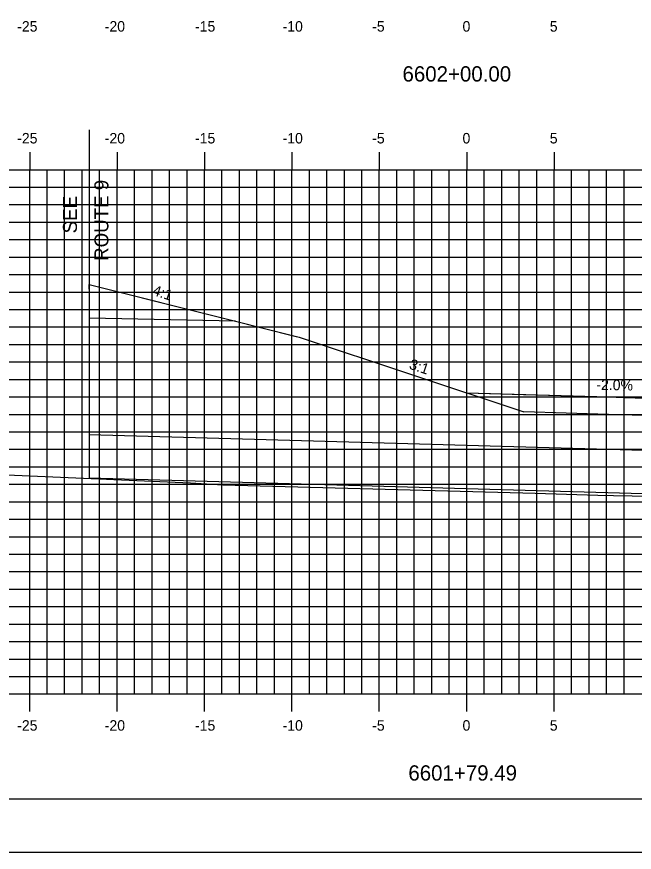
# Model space of a CAD drawing. Extents: x 1723961 to 1724133, y 459560 to 459670.
# Drawn here: x 1724018.73 to 1724054.06, y 459559.55 to 459607.37 of the extents above; entities that cross this region are included whole.
import ezdxf

# ---------------------------------------------------------------- set-up
doc = ezdxf.new("R2010")
doc.units = 0
for name, color, linetype in [('ANNOTATION', 7, 'Continuous'), ('BORDER', 7, 'Continuous'), ('D_Drainage_Culvert', 7, 'Continuous'), ('D_Roadway_Centerline', 7, 'Continuous'), ('D_Roadway_Drive_Gravel', 7, 'Continuous'), ('D_Roadway_Edge_Shoulder', 7, 'Continuous'), ('D_Roadway_SlopeLines', 7, 'Continuous'), ('D_Roadway_SubGrade', 7, 'Continuous'), ('H_V ANNOTATION', 7, 'Continuous'), ('MAJOR', 7, 'Continuous'), ('MINOR', 7, 'Continuous'), ('PLOT BOUNDARY', 7, 'Continuous'), ('S_Roadway_Centerline', 7, 'Continuous')]:
    doc.layers.add(name, color=color, linetype=linetype)

msp = doc.modelspace()

# ---------------------------------------------------------------- linework, layer by layer
msp.add_lwpolyline([(1724044.473, 459585.843), (1724047.721, 459585.749), (1724049.861, 459585.686), (1724052.573, 459585.607), (1724053.432, 459585.582), (1724054.109, 459585.562), (1724059.84, 459585.395), (1724060.497, 459585.376), (1724060.574, 459585.374), (1724060.673, 459585.371), (1724062.76, 459584.665), (1724063.904, 459584.277), (1724067.586, 459583.03)])
at = {"layer": 'BORDER'}
msp.add_lwpolyline([(1723969.473, 459562.613), (1724129.473, 459562.613), (1724129.473, 459667.613), (1723969.473, 459667.613)], close=True, dxfattribs=at)
at = {"layer": 'D_Drainage_Culvert'}
msp.add_lwpolyline([(1724022.879, 459583.464), (1724077.547, 459581.919), (1724077.48, 459579.42), (1724022.879, 459580.963)], dxfattribs=at)
at = {"layer": 'D_Roadway_Centerline'}
msp.add_lwpolyline([(1724022.879, 459592.034), (1724030.709, 459590.077), (1724031.241, 459589.944), (1724034.647, 459589.092), (1724034.879, 459589.034), (1724047.738, 459584.748)], dxfattribs=at)
at = {"layer": 'D_Roadway_Drive_Gravel'}
msp.add_lwpolyline([(1724044.473, 459585.836), (1724044.473, 459585.843), (1724052.573, 459585.607), (1724060.673, 459585.371), (1724063.904, 459584.277), (1724060.673, 459584.371), (1724052.573, 459584.607), (1724047.738, 459584.748)], dxfattribs=at)
at = {"layer": 'D_Roadway_Edge_Shoulder'}
msp.add_line((1724022.879, 459592.034), (1724022.879, 459591.784), dxfattribs=at)
msp.add_line((1724022.879, 459592.034), (1724022.879, 459591.784), dxfattribs=at)
at = {"layer": 'D_Roadway_SlopeLines'}
msp.add_lwpolyline([(1724022.879, 459592.034), (1724034.879, 459589.034), (1724047.738, 459584.748)], dxfattribs=at)
msp.add_lwpolyline([(1724022.879, 459592.034), (1724034.879, 459589.034), (1724047.738, 459584.748)], dxfattribs=at)
msp.add_lwpolyline([(1724022.879, 459592.034), (1724034.879, 459589.034), (1724047.738, 459584.748)], dxfattribs=at)
msp.add_lwpolyline([(1724022.879, 459592.034), (1724034.879, 459589.034), (1724047.738, 459584.748)], dxfattribs=at)
msp.add_lwpolyline([(1724022.879, 459592.034), (1724034.879, 459589.034), (1724047.738, 459584.748)], dxfattribs=at)
msp.add_lwpolyline([(1724022.879, 459592.034), (1724034.879, 459589.034), (1724047.738, 459584.748)], dxfattribs=at)
msp.add_lwpolyline([(1724022.879, 459592.034), (1724034.879, 459589.034), (1724047.738, 459584.748)], dxfattribs=at)
at = {"layer": 'D_Roadway_SubGrade'}
for p, q in [((1724022.879, 459600.893), (1724022.879, 459590.111)), ((1724022.879, 459590.111), (1724022.879, 459580.941))]:
    msp.add_line(p, q, dxfattribs=at)
msp.add_lwpolyline([(1724022.879, 459591.784), (1724022.879, 459592.034), (1724031.241, 459589.944), (1724022.879, 459590.111)], dxfattribs=at)
msp.add_lwpolyline([(1724022.879, 459591.784), (1724022.879, 459592.034), (1724031.241, 459589.944), (1724022.879, 459590.111)], dxfattribs=at)
msp.add_lwpolyline([(1724022.879, 459591.784), (1724022.879, 459592.034), (1724031.241, 459589.944), (1724022.879, 459590.111)], dxfattribs=at)
msp.add_lwpolyline([(1724022.879, 459591.784), (1724022.879, 459592.034), (1724031.241, 459589.944), (1724022.879, 459590.111)], dxfattribs=at)
at = {"layer": 'MAJOR'}
for p, q in [((1724019.473, 459599.615), (1724019.473, 459598.613)), ((1724024.473, 459599.615), (1724024.473, 459598.613)), ((1724029.473, 459599.615), (1724029.473, 459598.613)), ((1724034.473, 459599.615), (1724034.473, 459598.613)), ((1724039.473, 459599.615), (1724039.473, 459598.613)), ((1724044.473, 459599.615), (1724044.473, 459598.613)), ((1724049.473, 459599.615), (1724049.473, 459598.613)), ((1723974.473, 459598.613), (1724114.473, 459598.613)), ((1723974.473, 459598.613), (1724114.473, 459598.613)), ((1724019.473, 459568.613), (1724019.473, 459598.613)), ((1724024.473, 459568.613), (1724024.473, 459598.613)), ((1724029.473, 459568.613), (1724029.473, 459598.613)), ((1724034.473, 459568.613), (1724034.473, 459598.613)), ((1724039.473, 459568.613), (1724039.473, 459598.613)), ((1724044.473, 459568.613), (1724044.473, 459598.613)), ((1724049.473, 459568.613), (1724049.473, 459598.613)), ((1723974.473, 459593.613), (1724114.473, 459593.613)), ((1723974.473, 459588.613), (1724114.473, 459588.613)), ((1723974.473, 459583.613), (1724114.473, 459583.613)), ((1723974.473, 459578.613), (1724114.473, 459578.613)), ((1723974.473, 459573.613), (1724114.473, 459573.613)), ((1723974.473, 459568.613), (1724114.473, 459568.613)), ((1723974.473, 459568.613), (1724114.473, 459568.613)), ((1724019.473, 459567.611), (1724019.473, 459568.613)), ((1724024.473, 459567.611), (1724024.473, 459568.613)), ((1724029.473, 459567.611), (1724029.473, 459568.613)), ((1724034.473, 459567.611), (1724034.473, 459568.613)), ((1724039.473, 459567.611), (1724039.473, 459568.613)), ((1724044.473, 459567.611), (1724044.473, 459568.613)), ((1724049.473, 459567.611), (1724049.473, 459568.613))]:
    msp.add_line(p, q, dxfattribs=at)
at = {"layer": 'MINOR'}
for p, q in [((1724020.473, 459568.613), (1724020.473, 459598.613)), ((1724021.473, 459568.613), (1724021.473, 459598.613)), ((1724022.473, 459568.613), (1724022.473, 459598.613)), ((1724023.473, 459568.613), (1724023.473, 459598.613)), ((1724025.473, 459568.613), (1724025.473, 459598.613)), ((1724026.473, 459568.613), (1724026.473, 459598.613)), ((1724027.473, 459568.613), (1724027.473, 459598.613)), ((1724028.473, 459568.613), (1724028.473, 459598.613)), ((1724030.473, 459568.613), (1724030.473, 459598.613)), ((1724031.473, 459568.613), (1724031.473, 459598.613)), ((1724032.473, 459568.613), (1724032.473, 459598.613)), ((1724033.473, 459568.613), (1724033.473, 459598.613)), ((1724035.473, 459568.613), (1724035.473, 459598.613)), ((1724036.473, 459568.613), (1724036.473, 459598.613)), ((1724037.473, 459568.613), (1724037.473, 459598.613)), ((1724038.473, 459568.613), (1724038.473, 459598.613)), ((1724040.473, 459568.613), (1724040.473, 459598.613)), ((1724041.473, 459568.613), (1724041.473, 459598.613)), ((1724042.473, 459568.613), (1724042.473, 459598.613)), ((1724043.473, 459568.613), (1724043.473, 459598.613)), ((1724045.473, 459568.613), (1724045.473, 459598.613)), ((1724046.473, 459568.613), (1724046.473, 459598.613)), ((1724047.473, 459568.613), (1724047.473, 459598.613)), ((1724048.473, 459568.613), (1724048.473, 459598.613)), ((1724050.473, 459568.613), (1724050.473, 459598.613)), ((1724051.473, 459568.613), (1724051.473, 459598.613)), ((1724052.473, 459568.613), (1724052.473, 459598.613)), ((1724053.473, 459568.613), (1724053.473, 459598.613)), ((1723974.473, 459597.613), (1724114.473, 459597.613)), ((1723974.473, 459596.613), (1724114.473, 459596.613)), ((1723974.473, 459595.613), (1724114.473, 459595.613)), ((1723974.473, 459594.613), (1724114.473, 459594.613)), ((1723974.473, 459592.613), (1724114.473, 459592.613)), ((1723974.473, 459591.613), (1724114.473, 459591.613)), ((1723974.473, 459590.613), (1724114.473, 459590.613)), ((1723974.473, 459589.613), (1724114.473, 459589.613)), ((1723974.473, 459587.613), (1724114.473, 459587.613)), ((1723974.473, 459586.613), (1724114.473, 459586.613)), ((1723974.473, 459585.613), (1724114.473, 459585.613)), ((1723974.473, 459584.613), (1724114.473, 459584.613)), ((1723974.473, 459582.613), (1724114.473, 459582.613)), ((1723974.473, 459581.613), (1724114.473, 459581.613)), ((1723974.473, 459580.613), (1724114.473, 459580.613)), ((1723974.473, 459579.613), (1724114.473, 459579.613)), ((1723974.473, 459577.613), (1724114.473, 459577.613)), ((1723974.473, 459576.613), (1724114.473, 459576.613)), ((1723974.473, 459575.613), (1724114.473, 459575.613)), ((1723974.473, 459574.613), (1724114.473, 459574.613)), ((1723974.473, 459572.613), (1724114.473, 459572.613)), ((1723974.473, 459571.613), (1724114.473, 459571.613)), ((1723974.473, 459570.613), (1724114.473, 459570.613)), ((1723974.473, 459569.613), (1724114.473, 459569.613))]:
    msp.add_line(p, q, dxfattribs=at)
at = {"layer": 'PLOT BOUNDARY'}
msp.add_lwpolyline([(1723961.38, 459559.554), (1724131.38, 459559.554), (1724131.38, 459669.554), (1723961.38, 459669.554)], close=True, dxfattribs=at)
at = {"layer": 'S_Roadway_Centerline'}
msp.add_lwpolyline([(1723974.473, 459582.674), (1723975.565, 459582.628), (1723981.882, 459582.172), (1723988.93, 459581.994), (1723994.928, 459581.861), (1724001.466, 459581.651), (1724009.838, 459581.512), (1724028.663, 459580.689), (1724030.526, 459580.584), (1724048.383, 459580.095), (1724051.968, 459579.995), (1724052.877, 459579.975), (1724072.141, 459579.635), (1724078.313, 459579.386), (1724087.228, 459578.819), (1724094.374, 459578.663), (1724104.996, 459578.514), (1724110.799, 459578.473), (1724114.473, 459578.399)], dxfattribs=at)

# ---------------------------------------------------------------- texts
at = {"layer": 'ANNOTATION'}
for s, height, rotation, p in [('ROUTE 9', 0.8, 90, (1724023.976, 459593.393)), ('SEE', 0.8, 90, (1724022.176, 459594.968)), ('4:1', 0.6, 341.5651, (1724026.456, 459591.462)), ('3:1', 0.6, 341.5651, (1724041.138, 459587.235)), ('-2.0%', 0.6, 358.8542, (1724051.881, 459586.017))]:
    msp.add_text(s, height=height, rotation=rotation, dxfattribs=at).set_placement(p)
at = {"layer": 'H_V ANNOTATION'}
for s, height, p in [('-25', 0.6, (1724018.759, 459606.513)), ('-20', 0.6, (1724023.767, 459606.513)), ('-15', 0.6, (1724028.93, 459606.513)), ('-10', 0.6, (1724033.938, 459606.513)), ('-5', 0.6, (1724039.064, 459606.513)), ('0', 0.6, (1724044.232, 459606.513)), ('5', 0.6, (1724049.224, 459606.513)), ('6602+00.00', 0.875, (1724040.798, 459603.656)), ('-25', 0.6, (1724018.759, 459600.113)), ('-20', 0.6, (1724023.767, 459600.113)), ('-15', 0.6, (1724028.93, 459600.113)), ('-10', 0.6, (1724033.938, 459600.113)), ('-5', 0.6, (1724039.064, 459600.113)), ('0', 0.6, (1724044.232, 459600.113)), ('5', 0.6, (1724049.224, 459600.113)), ('-25', 0.6, (1724018.759, 459566.513)), ('-20', 0.6, (1724023.767, 459566.513)), ('-15', 0.6, (1724028.93, 459566.513)), ('-10', 0.6, (1724033.938, 459566.513)), ('-5', 0.6, (1724039.064, 459566.513)), ('0', 0.6, (1724044.232, 459566.513)), ('5', 0.6, (1724049.224, 459566.513)), ('6601+79.49', 0.875, (1724041.134, 459563.656))]:
    msp.add_text(s, height=height, dxfattribs=at).set_placement(p)

doc.saveas('drawing.dxf')
